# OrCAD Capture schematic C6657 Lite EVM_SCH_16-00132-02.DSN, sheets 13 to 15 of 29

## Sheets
13 PAGE13 : DSP_SERDES_PORTS: size C; title: DSP SERDES PORTS
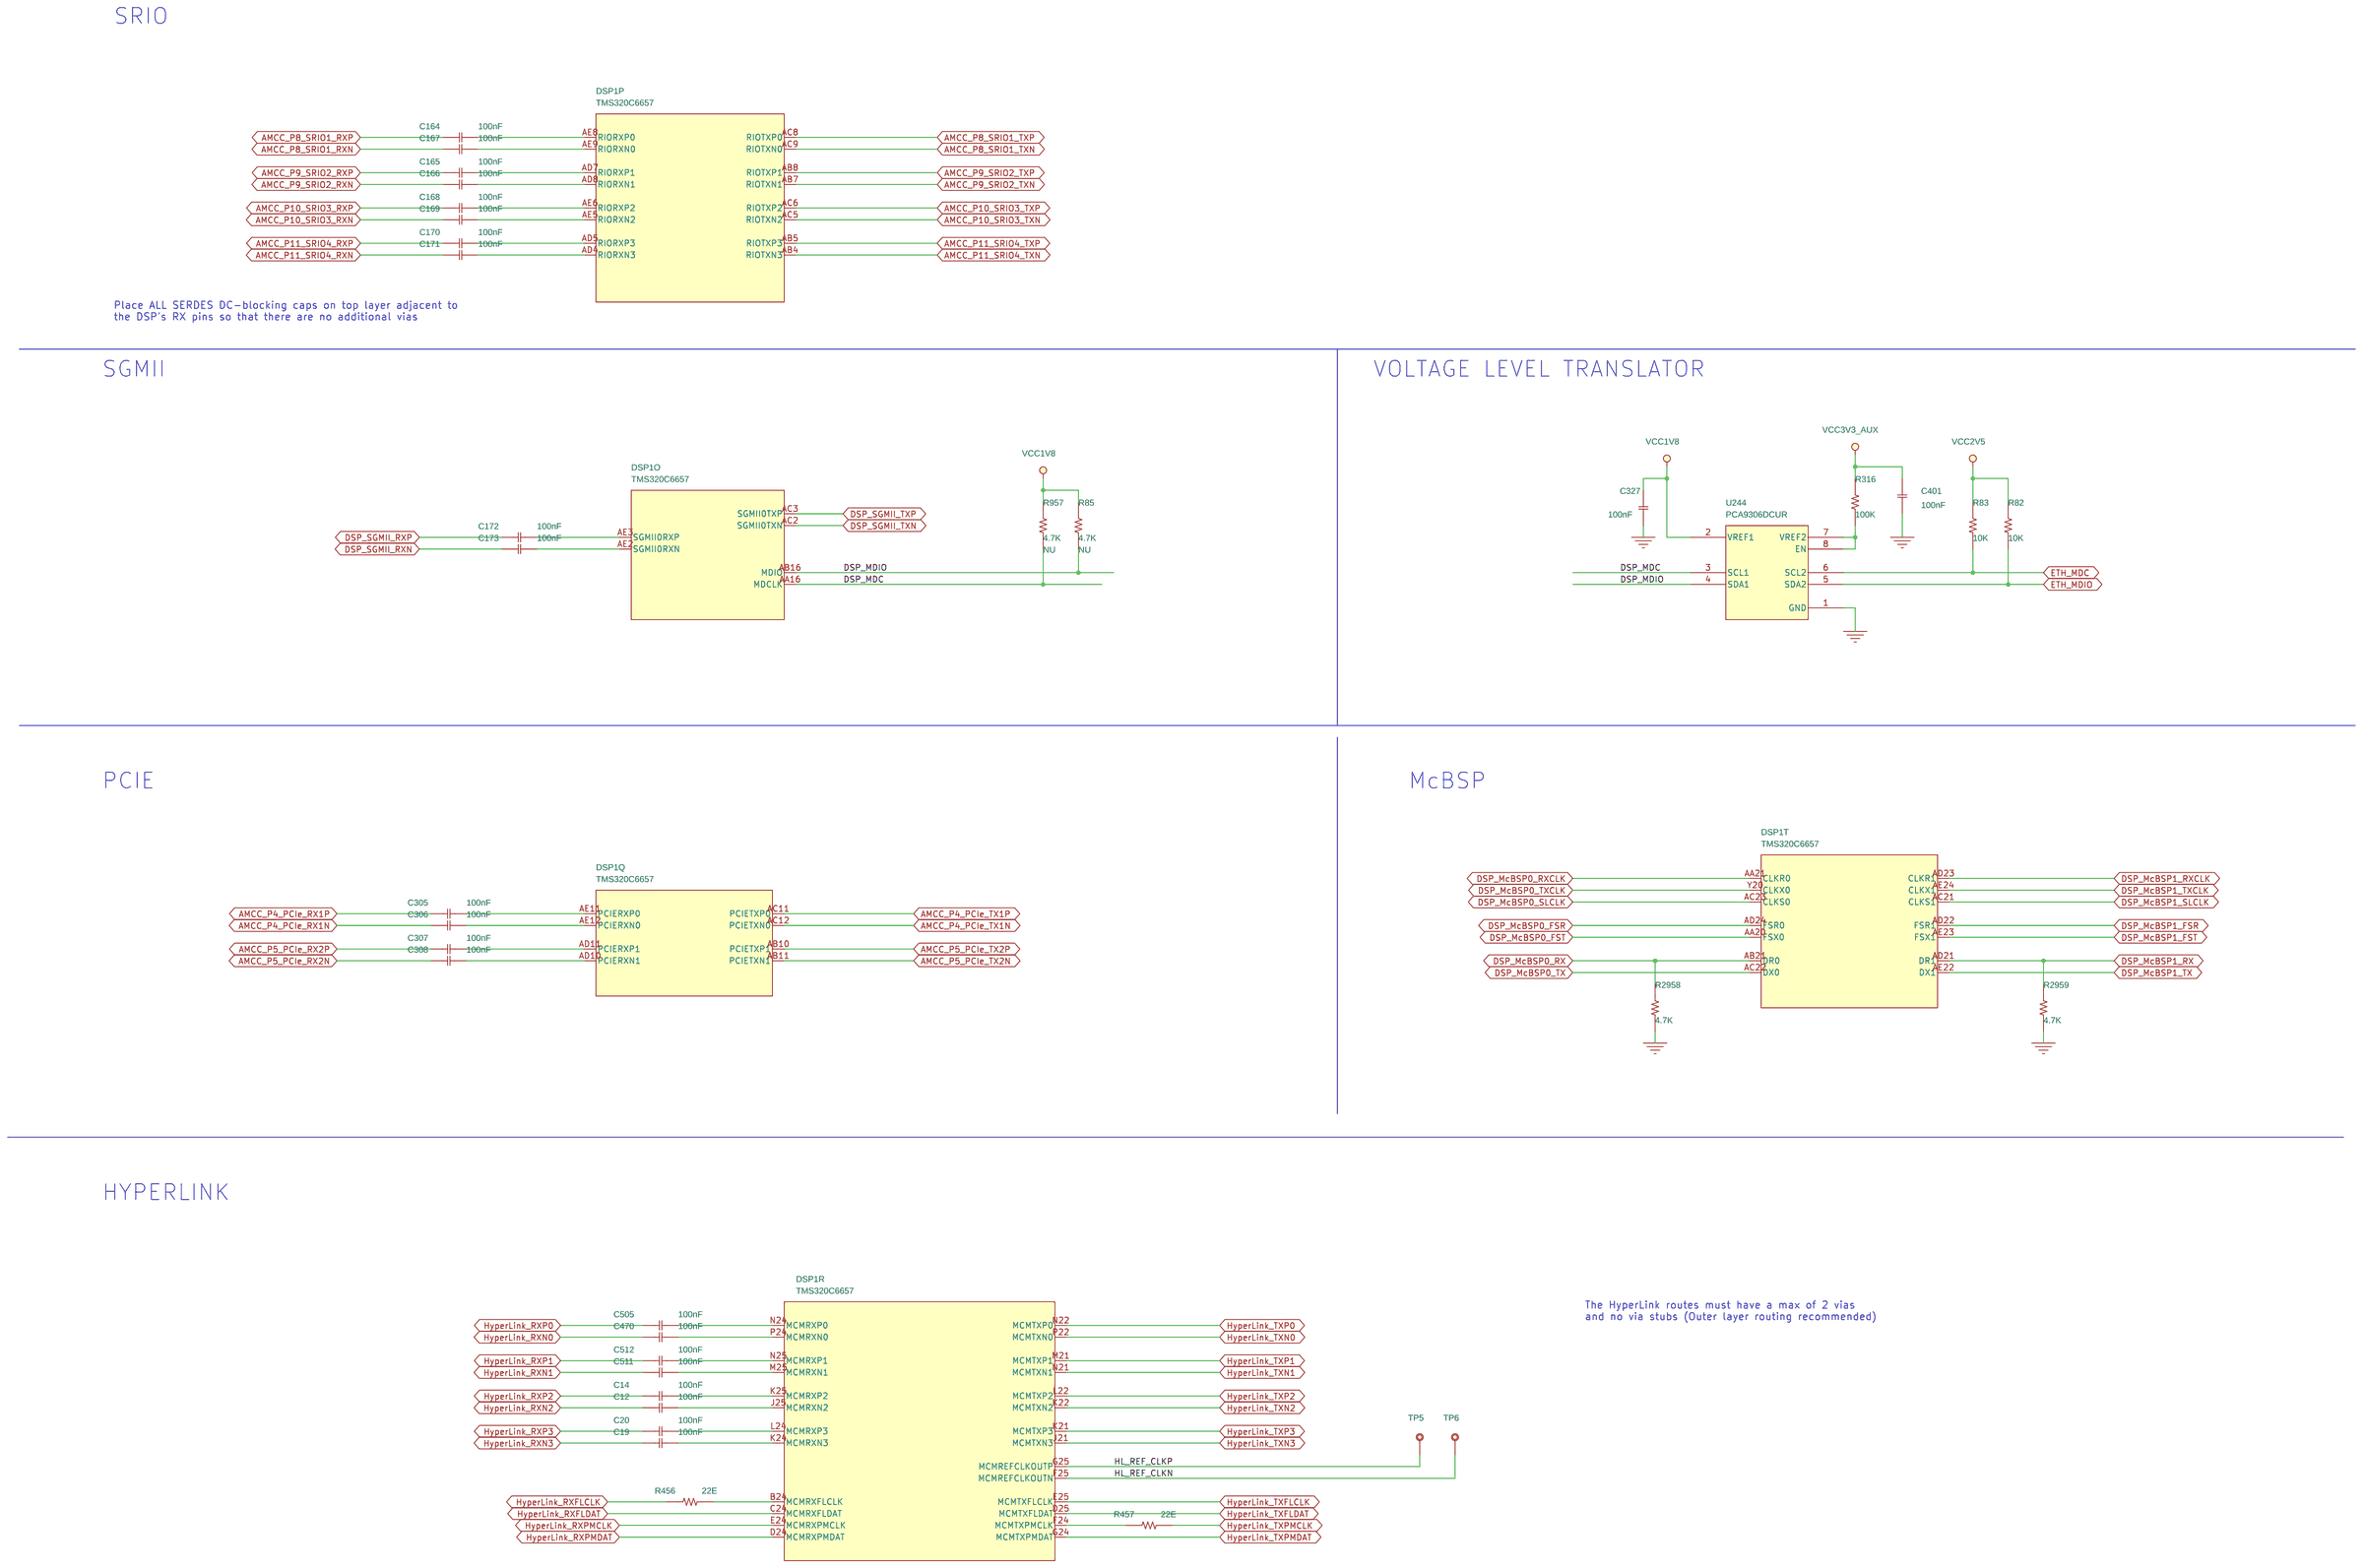
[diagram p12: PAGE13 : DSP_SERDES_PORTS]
14 PAGE27 : POWER SUPPLY 1: size C; title: POWER SUPPLY 1
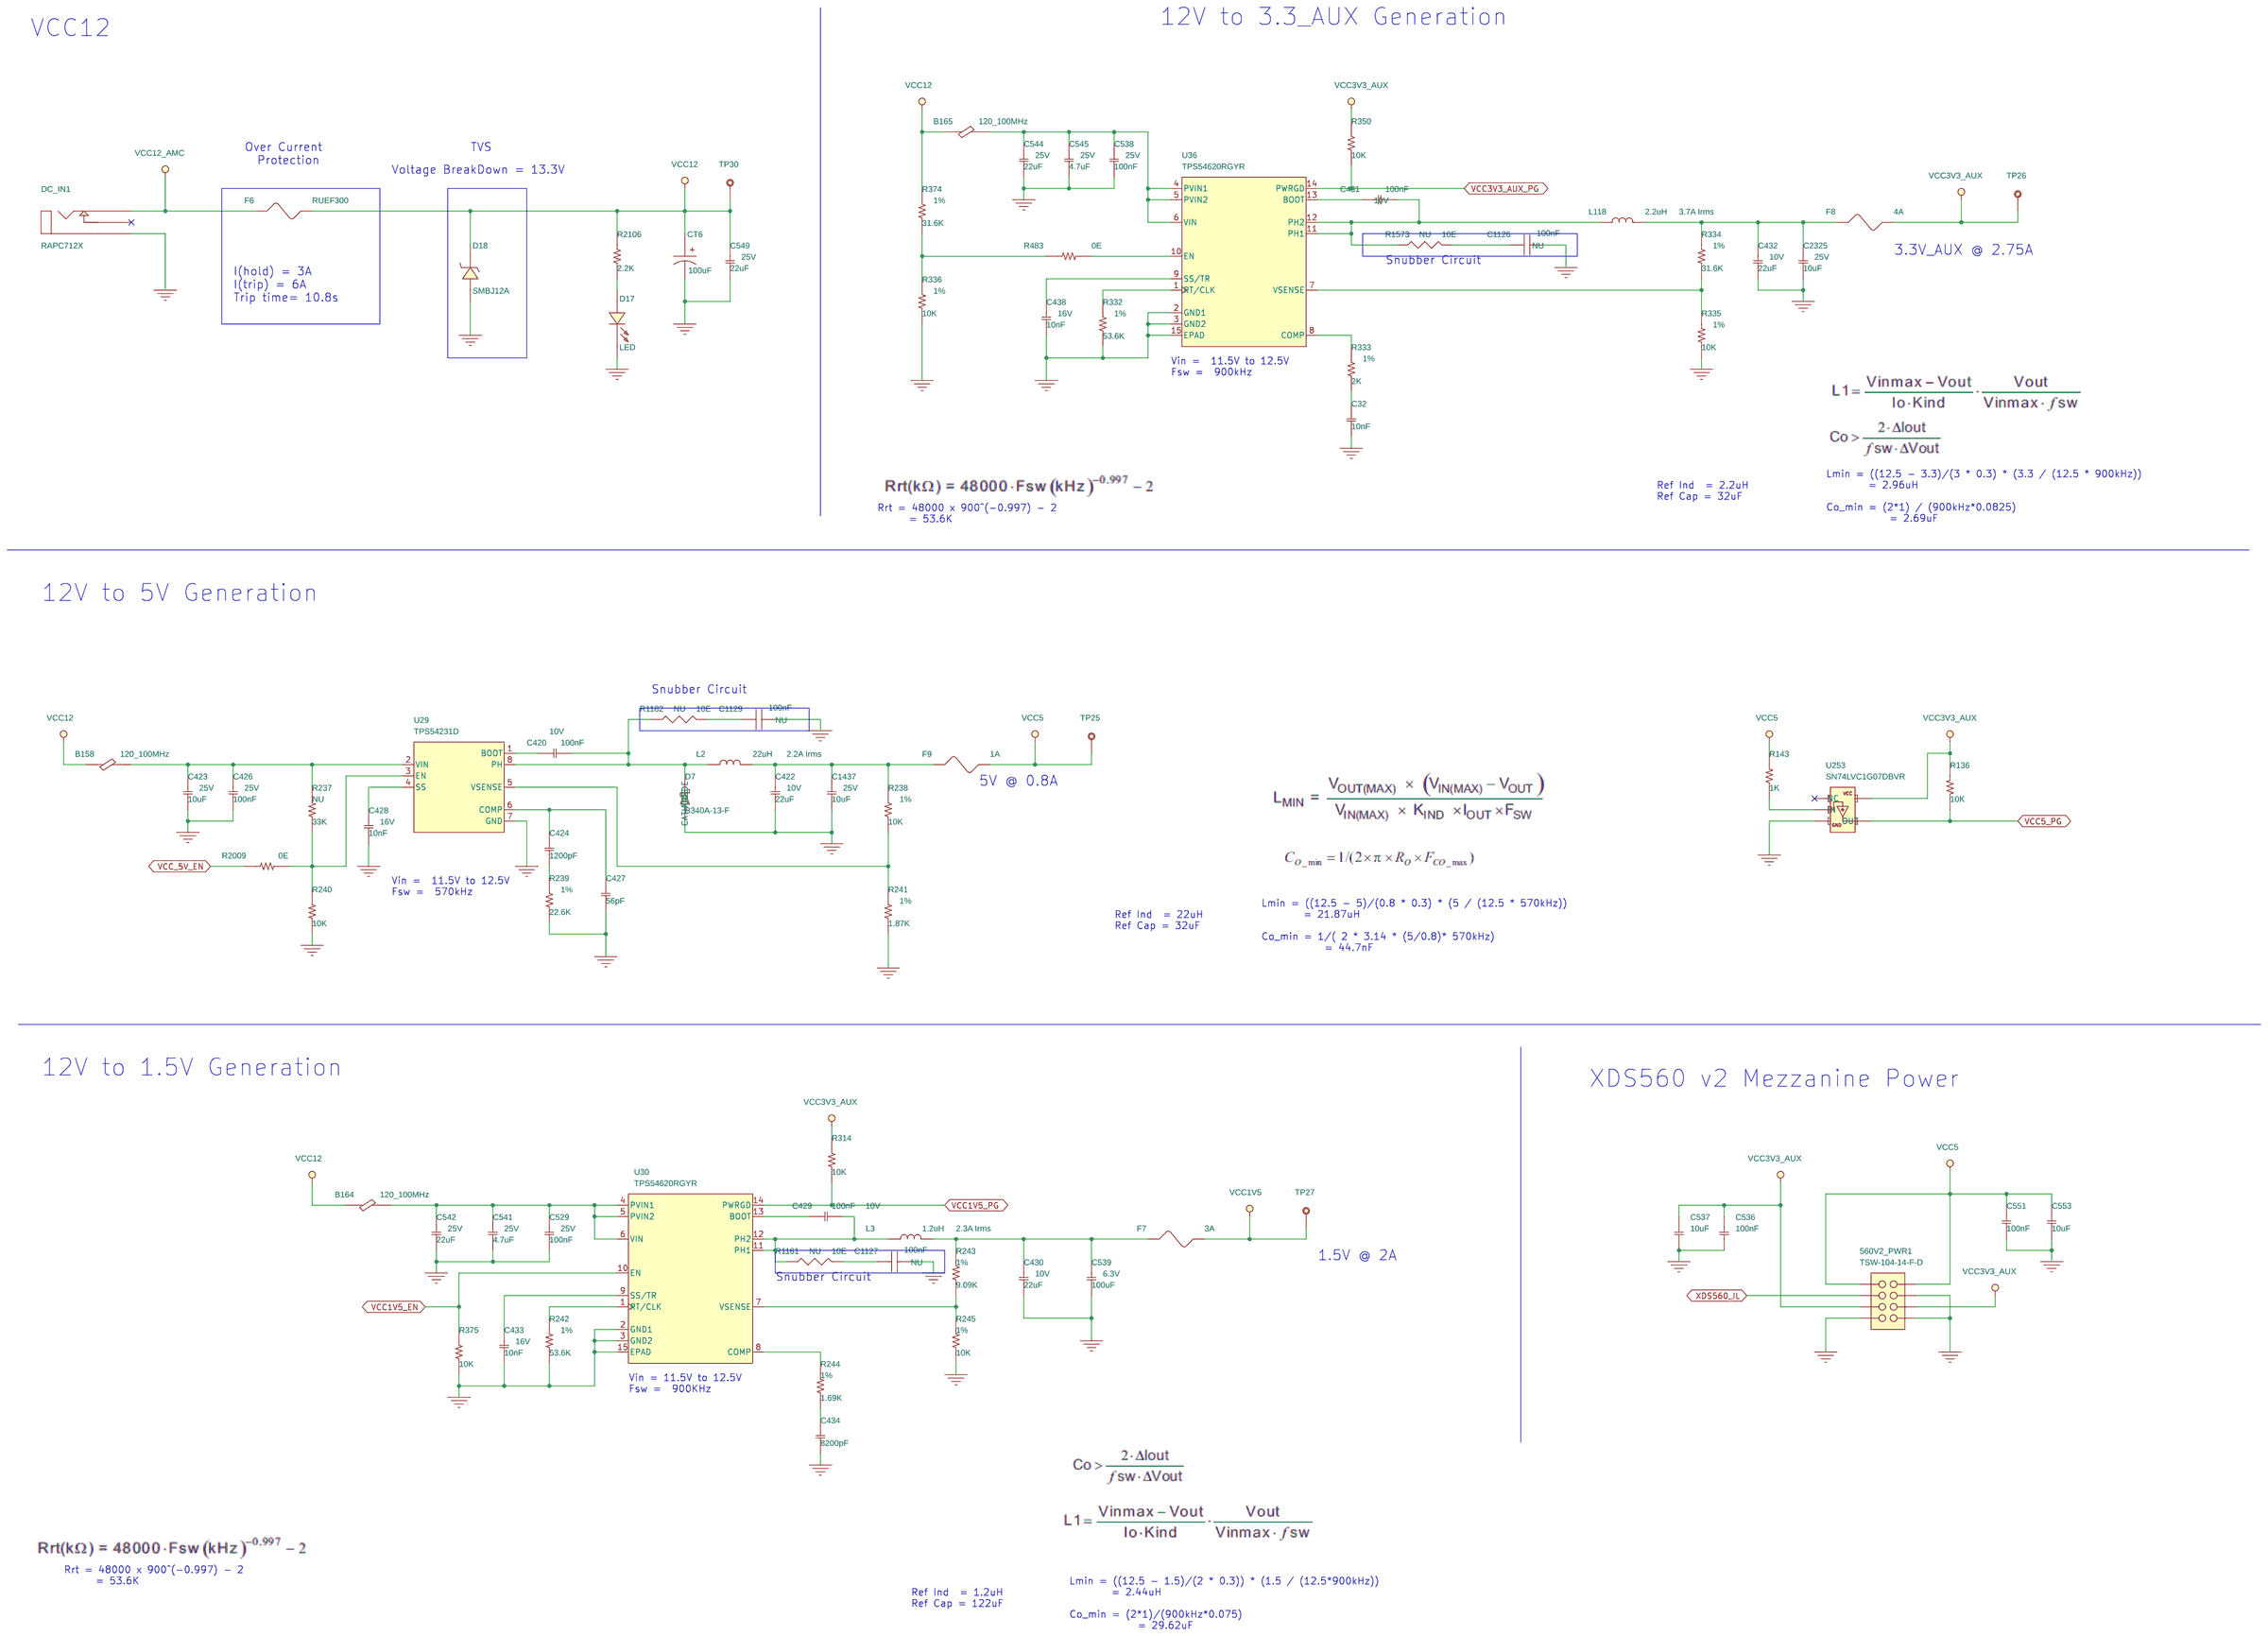
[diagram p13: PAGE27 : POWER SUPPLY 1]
15 PAGE28 : POWER SUPPLY 2: size C; title: POWER SUPPLY 2
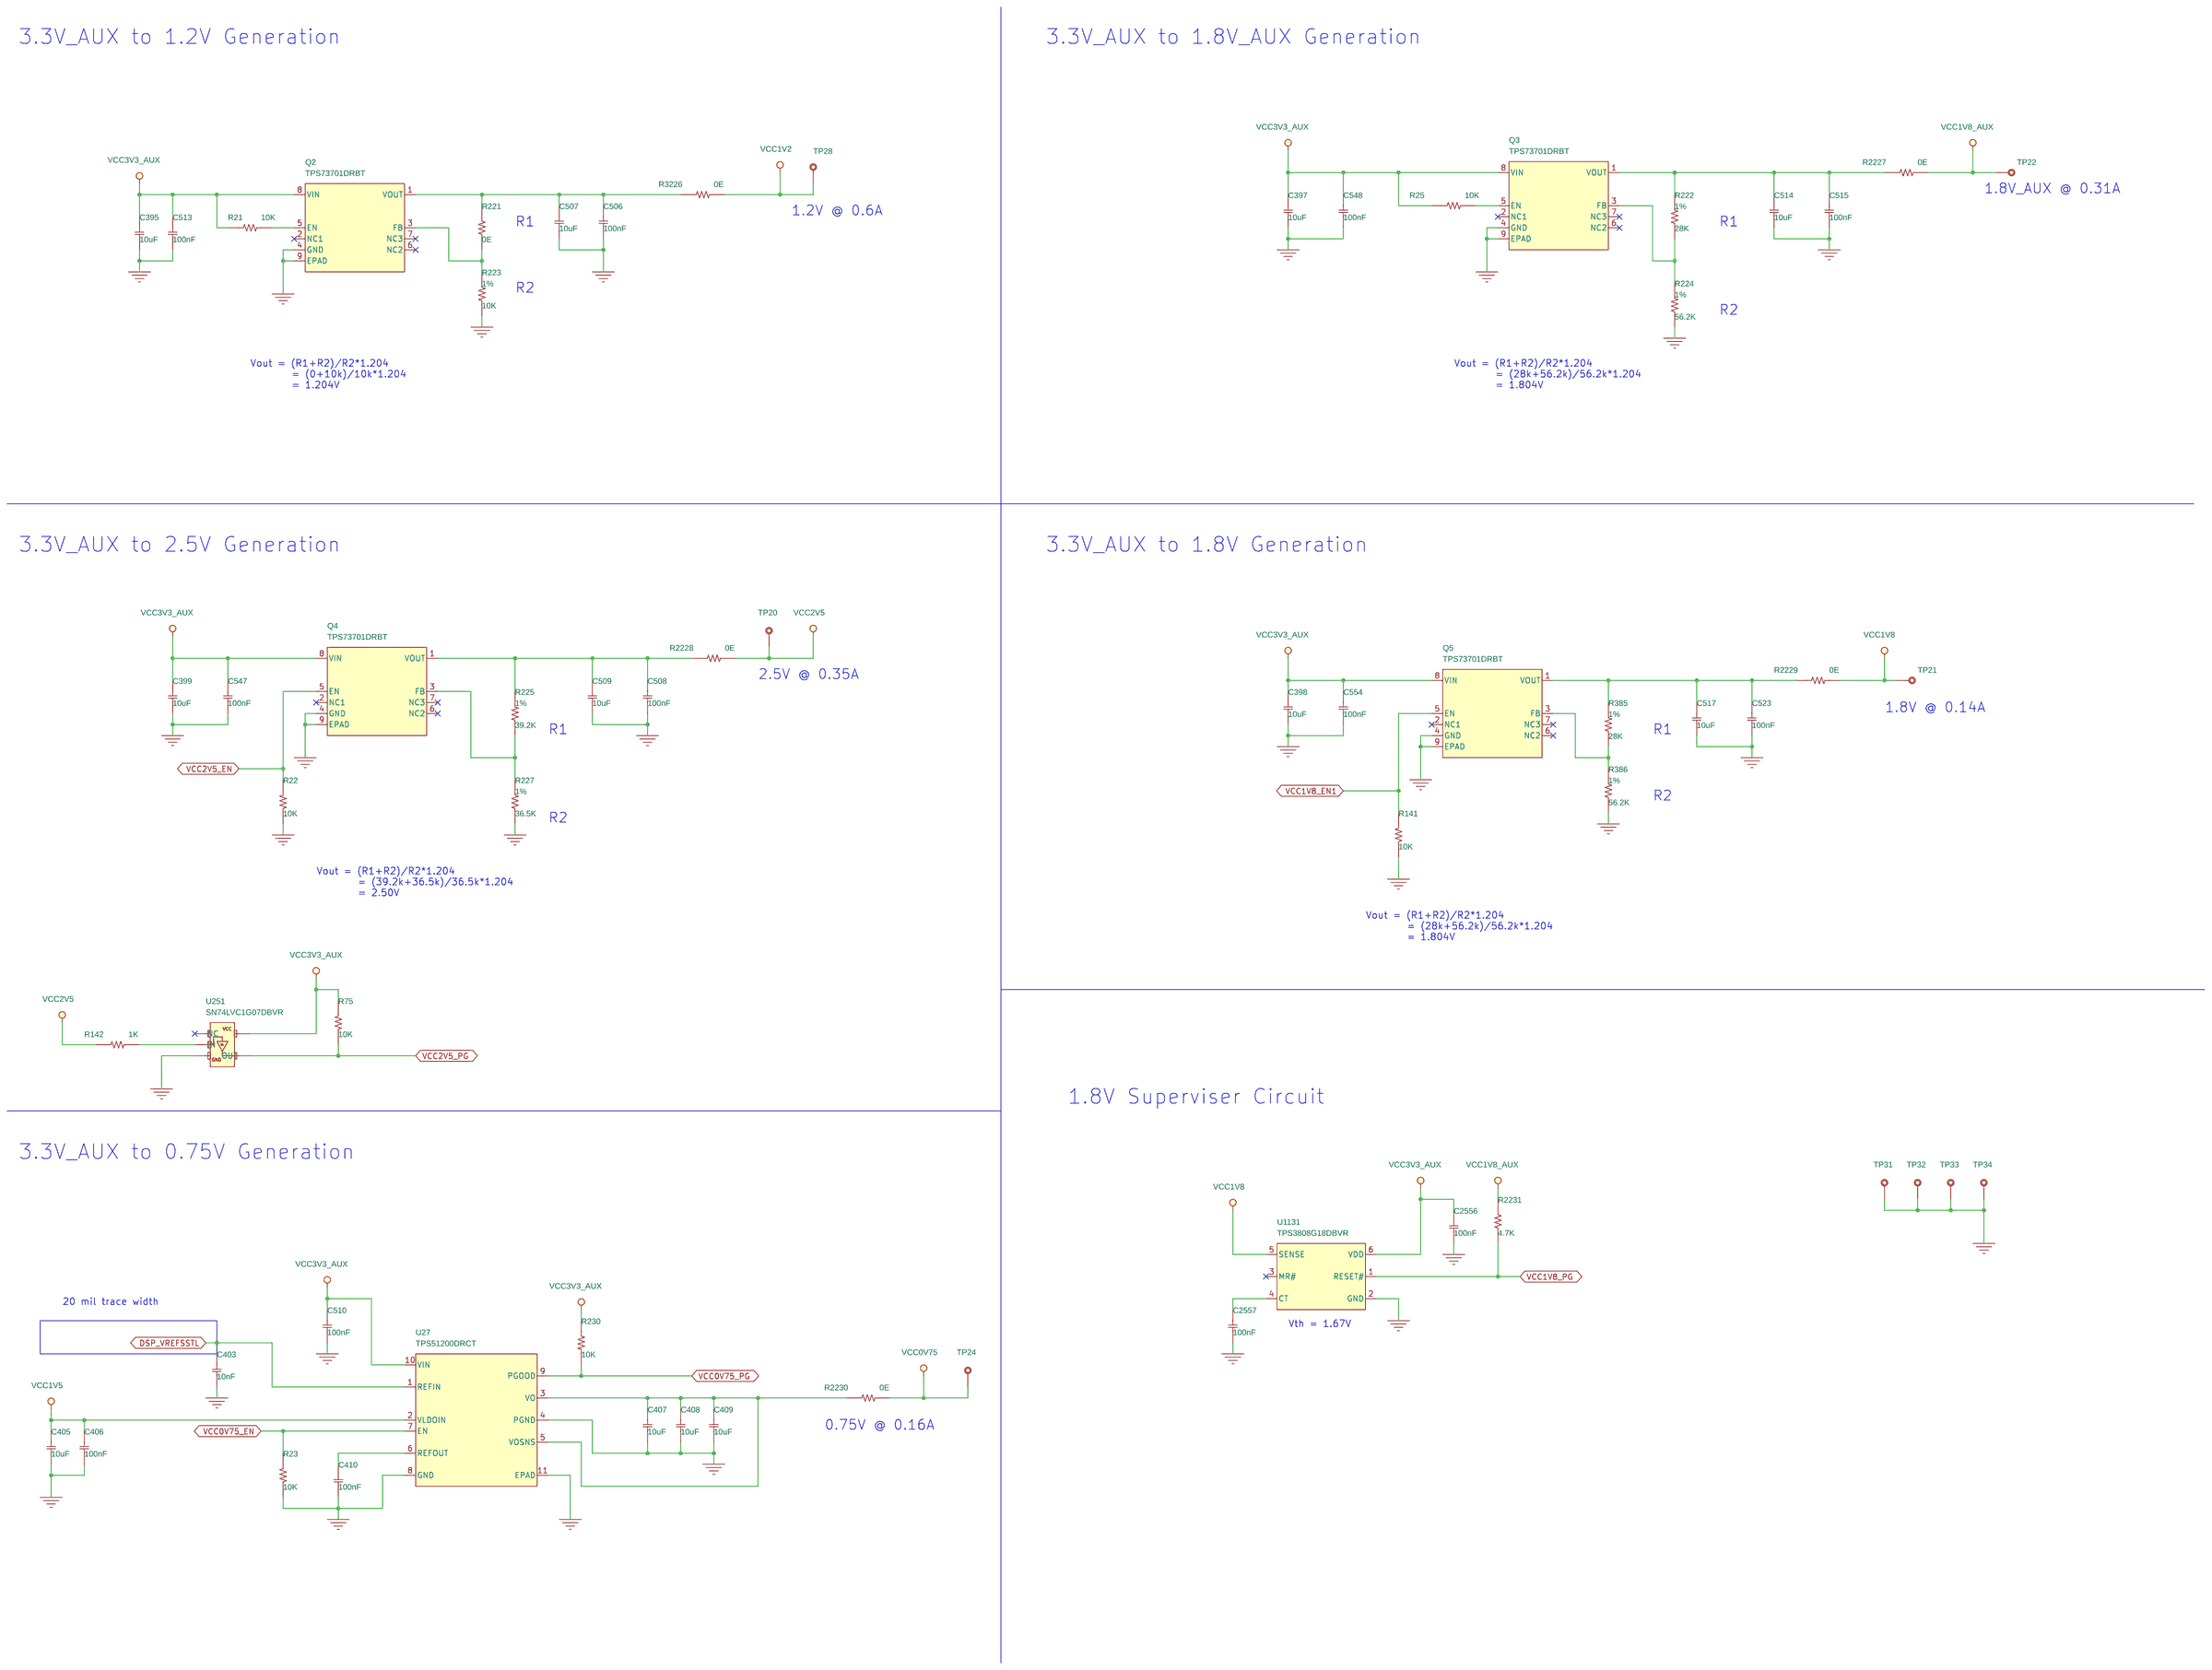
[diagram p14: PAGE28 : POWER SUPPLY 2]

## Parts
sheet PAGE13 : DSP_SERDES_PORTS
C12  100nF  [C0402]
C14  100nF  [C0402]
C19  100nF  [C0402]
C20  100nF  [C0402]
C164  100nF  [C0402]
C165  100nF  [C0402]
C166  100nF  [C0402]
C167  100nF  [C0402]
C168  100nF  [C0402]
C169  100nF  [C0402]
C170  100nF  [C0402]
C171  100nF  [C0402]
C172  100nF  [C0402]
C173  100nF  [C0402]
C305  100nF  [C0402]
C306  100nF  [C0402]
C307  100nF  [C0402]
C308  100nF  [C0402]
C327  100nF  [C0402]
C401  100nF  [C0402]
C470  100nF  [C0402]
C505  100nF  [C0402]
C511  100nF  [C0402]
C512  100nF  [C0402]
R82  10K  [R0402]
R83  10K  [R0402]
R85  4.7K  [R0402]
R316  100K  [R0402]
R456  22E  [R0402]
R457  22E  [R0402]
R957  4.7K  [R0402]
R2958  4.7K  [R0402]
R2959  4.7K  [R0402]
TP5  Test Point  [TP-S40]
TP6  Test Point  [TP-S40]
U244  PCA9306DCUR  [SOIC_8P_20_79X122]
sheet PAGE25 : DSP_POWER 2
DSP1  TMS320C6657  [BGA80P_38X38_625_SKT_EINF]  (sections A,B,C,D,E,F,G,H,I,J,K,L,M,N,O,P,Q,R,S,T)
sheet PAGE27 : POWER SUPPLY 1
560V2_PWR1  TSW-104-14-F-D  [HD_4x2P_100_D]
B158  120_100MHz  [L0603]
B164  120_100MHz  [L0603]
B165  120_100MHz  [L0603]
C32  10nF  [C0402]
C420  100nF  [C0402]
C422  22uF  [C0805]
C423  10uF  [C0805]
C424  1200pF  [C0402]
C426  100nF  [C0402]
C427  56pF  [C0603]
C428  10nF  [C0402]
C429  100nF  [C0402]
C430  22uF  [C0805]
C431  100nF  [C0402]
C432  22uF  [C0805]
C433  10nF  [C0402]
C434  8200pF  [C0603]
C438  10nF  [C0402]
C529  100nF  [C0402]
C536  100nF  [C0402]
C537  10uF  [C0603]
C538  100nF  [C0402]
C539  100uF  [C1206-1]
C541  4.7uF  [C0805]
C542  22uF  [C1206-1]
C544  22uF  [C1206-1]
C545  4.7uF  [C0805]
C549  22uF  [C1206-1]
C551  100nF  [C0402]
C553  10uF  [C0805]
C1126  100nF  [C0402]
C1127  100nF  [C0402]
C1129  100nF  [C0402]
C1437  10uF  [C0805]
C2325  10uF  [C0805]
CT6  100uF  [CT7343]
D7  B340A-13-F  [DIODE_2P_158_197X110]
D17  LED  [LED_LTST-C171]
D18  SMBJ12A  [DIO_DO214AA_SMB]
DC_IN1  RAPC712X  [CON_RAPC712_PWRJACK]
F6  RUEF300  [PTC_RUEF300]
F7  F0603E3R00FSTR  [FUSE_C0603]
F8  MFU0603FF04000P100  [FUSE_C0603]
F9  F0603E1R00FSTR  [FUSE_C0603]
L2  22uH  [IND_NR8040]
L3  1.2uH  [IND_NRG4026]
L118  2.2uH  [IND_NR6028]
R136  10K  [R0402]
R143  1K  [R0402]
R237  33K  [R0402]
R238  10K  [R0402]
R239  22.6K  [R0603]
R240  10K  [R0402]
R241  1.87K  [R0603]
R242  53.6K  [R0402]
R243  9.09K  [R0603]
R244  1.69K  [R0603]
R245  10K  [R0402]
R314  10K  [R0402]
R332  53.6K  [R0402]
R333  2K  [R0402]
R334  31.6K  [R0402]
R335  10K  [R0402]
R336  10K  [R0402]
R350  10K  [R0402]
R374  31.6K  [R0402]
R375  10K  [R0402]
R483  0E  [R0402]
R1181  10E  [R0402]
R1182  10E  [R0402]
R1573  10E  [R0402]
R2009  0E  [R0402]
R2106  2.2K  [R0402]
TP25  Test Point  [TP-S40]
TP26  Test Point  [TP-S40]
TP27  Test Point  [TP-S40]
TP30  Test Point  [TP-S40]
U29  TPS54231D  [SOIC_8P_50_193x236]
U30  TPS54620RGYR  [QFN_14P_20_138x138_TP79]
U36  TPS54620RGYR  [QFN_14P_20_138x138_TP79]
U253  SN74LVC1G07DBVR  [SOT-23_5P]
sheet PAGE28 : POWER SUPPLY 2
C395  10uF  [C0603]
C397  10uF  [C0603]
C398  10uF  [C0603]
C399  10uF  [C0603]
C403  10nF  [C0402]
C405  10uF  [C0603]
C406  100nF  [C0402]
C407  10uF  [C0603]
C408  10uF  [C0603]
C409  10uF  [C0603]
C410  100nF  [C0402]
C506  100nF  [C0402]
C507  10uF  [C0603]
C508  100nF  [C0402]
C509  10uF  [C0603]
C510  100nF  [C0402]
C513  100nF  [C0402]
C514  10uF  [C0603]
C515  100nF  [C0402]
C517  10uF  [C0603]
C523  100nF  [C0402]
C547  100nF  [C0402]
C548  100nF  [C0402]
C554  100nF  [C0402]
C2556  100nF  [C0402]
C2557  100nF  [C0402]
Q2  TPS73701DRBT  [QFN_8P_26_118x118]
Q3  TPS73701DRBT  [QFN_8P_26_118x118]
Q4  TPS73701DRBT  [QFN_8P_26_118x118]
Q5  TPS73701DRBT  [QFN_8P_26_118x118]
R21  10K  [R0402]
R22  10K  [R0402]
R23  10K  [R0402]
R25  10K  [R0402]
R75  10K  [R0402]
R141  10K  [R0402]
R142  1K  [R0402]
R221  0E  [R0402]
R222  28K  [R0603]
R223  10K  [R0402]
R224  56.2K  [R0603]
R225  39.2K  [R0603]
R227  36.5K  [R0603]
R230  10K  [R0402]
R385  28K  [R0603]
R386  56.2K  [R0603]
R2227  0E  [R0402]
R2228  0E  [R0402]
R2229  0E  [R0402]
R2230  0E  [R0402]
R2231  4.7K  [R0402]
R3226  0E  [R0402]
TP20  Test Point  [TP-S40]
TP21  Test Point  [TP-S40]
TP22  Test Point  [TP-S40]
TP24  Test Point  [TP-S40]
TP28  Test Point  [TP-S40]
TP31  Test Point  [TP-S40]
TP32  Test Point  [TP-S40]
TP33  Test Point  [TP-S40]
TP34  Test Point  [TP-S40]
U27  TPS51200DRCT  [QFN10P_20_118x118_TP94x65V5]
U251  SN74LVC1G07DBVR  [SOT-23_5P]
U1131  TPS3808G18DBVR  [SOT23_6]

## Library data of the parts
C12 C14 C19 C20 C164-C173 C305-C308 C327 C401 C406 C410 C470 C505 C506 C508 C510-C513 C515 C523 C536 C547 C548 C551 C554 C2556 C2557 = 11_C_0: CAP CER 0.1UF 10V 10% X5R 0402; Alt Mfg: Murata; Alt Mfg Part#: GRM155R61A104KA01D; Manufacture Part Number: 2238 787 15649||CC0402KRX7R7BB104; Mfg: Yageo; Mfg Part#: CC0402KRX5R6BB104; Oper. Temp. Range: -55C to 85C; Package: 0402; ProcessType: SMT; RoHS: Yes; Tolerance: 10%; Vendor: DigiKey; Vendor Part#: 311-1336-1-ND; eI Part#: 03_00021_02
R21-R23 R25 R75 R82 R83 R136 R141 R223 R230 R238 R240 R245 R314 R335 R336 R350 R375 = 10_R_0: RES 10.0K OHM 1/10W 1% 0402 SMD; Alt Mfg: Yageo; Alt Mfg Part#: RC0402FR-0710KL; Manufacture Part Number: 0402WGF1002TCE||RM04FTN1002; Mfg: Panasonic - ECG; Mfg Part#: ERJ-2RKF1002X; Oper. Temp. Range: -55C ~ 125C; Package: 0402; ProcessType: SMT; Remark: Alt part is 1/16W; RoHS: Yes; Tolerance: 1%; Vendor: DigiKey; Vendor Part#: P10.0KLCT-ND; eI Part#: 02_00027_01
R85 R957 = 10_R_0: RES 4.7K OHM 1/10W 5% 0402 SMD; Alt Mfg: Yageo; Alt Mfg Part#: RC0402JR-074K7L; Manufacture Part Number: 0402WGJ0472TCE||RC0402JR-074K7L||RM04JTN472; Mfg: Panasonic - ECG; Mfg Part#: ERJ-2GEJ472X; Mounting Status: NU; Mounting _Status: NU; Oper. Temp. Range: -55C to 125C; Package: 0402; ProcessType: SMT; Remark: Alt part is 1/16W; RoHS: Yes; Tolerance: 5%; Vendor: DigiKey; Vendor Part#: P4.7KJCT-ND; eI Part#: 02_00023_01
R316 = 10_R_0: RES 100K OHM 1/10W 1% 0402 SMD; Alt Mfg: Yageo; Alt Mfg Part#: RC0402FR-07100KL; Manufacture Part Number: 0402WGF1003TCE||RM04FTN1003; Mfg: Panasonic - ECG; Mfg Part#: ERJ-2RKF1003X; Oper. Temp. Range: ±100ppm/°C; Package: 0402; ProcessType: SMT; RoHS: Yes; Tolerance: 1%; Vendor: DigiKey; Vendor Part#: P100KLCT-ND; eI Part#: 02_00262_01
R456 R457 = 10_R_0: RES 22 OHM 1/10W 5% 0402 SMD; Mfg: Panasonic - ECG; Mfg Part#: ERJ-2GEJ220X; Oper. Temp. Range: -55C to 125C; Package: 0402; ProcessType: SMT; Remark: Alt part is 1/16W; RoHS: Yes; Tolerance: 5%; Vendor: DigiKey; Vendor Part#: P22JCT-ND; eI Part#: 02_00233_01
R2231 R2958 R2959 = 10_R_0: RES 4.7K OHM 1/10W 5% 0402 SMD; Alt Mfg: Yageo; Alt Mfg Part#: RC0402JR-074K7L; Manufacture Part Number: 0402WGJ0472TCE||RC0402JR-074K7L||RM04JTN472; Mfg: Panasonic - ECG; Mfg Part#: ERJ-2GEJ472X; Oper. Temp. Range: -55C to 125C; Package: 0402; ProcessType: SMT; Remark: Alt part is 1/16W; RoHS: Yes; Tolerance: 5%; Vendor: DigiKey; Vendor Part#: P4.7KJCT-ND; eI Part#: 02_00023_01
TP5 TP6 TP20-TP22 TP24-TP28 TP30-TP34 = 00_TP-S40_0: TEST PAD TP-S40; Mfg: --NA--; Mfg Part#: --NA--; Oper. Temp. Range: --NA--; Package: --NA--; ProcessType: SMT; RoHS: Yes; Vendor: --NA--; Vendor Part#: --NA--; eI Part#: --NA--
U244 = PCA9306: IC, Dual I2C Voltage Translator; Alt Mfg: NXP Semiconductors; Alt Mfg Part#: PCA9306DC1,125; Mfg: Texas Instruments; Oper. Temp. Range: -40C to 85C; Package: 8-VSSOP; RoHS: Yes; Specifications: IC, Dual I2C Voltage Translator; Vendor: Digikey; Vendor Part#: 296-17988-1-ND; eI Part#: 01_00044_01
DSP1 = TMS320C6657: TI DSP, Dual C66x™ DSP Cores; Mfg: Texas Instruments; RoHS: Yes; Vendor: Texas Instruments; eI Part#: 01_00878_01
560V2_PWR1 = CONNECTOR_-_4_X_2: HEADER, 2.54MM, THT VERT, 8WAY; Mfg: Samtec; Oper. Temp. Range: -55C to 125C; RoHS: Yes; Specifications: HEADER, 2.54MM, THT VERT, 8WAY; Vendor: Samtec; eI Part#: 09_00667_01
B158 B164 B165 = 1212_BEAD_0: FERRITE CHIP 120 OHM 2000MA 0603; Manufacture Part Number: BLM18PG121SN1; Mfg: Murata; Mfg Part#: BLM18PG121SN1D; Oper. Temp. Range: -55C to 85C; Package: 0603; ProcessType: SMT; RoHS: Yes; Tolerance: 25%; Vendor: DigiKey; Vendor Part#: 490-1037-1-ND; eI Part#: 04_00023_01
C32 = 11_C_0: CAP 10nF 16V CERAMIC 0402 SMD; Alt Mfg: Murata; Alt Mfg Part#: GRM155R71C103KA01D; Mfg: Panasonic - ECG; Mfg Part#: ECJ-0EB1C103K; Oper. Temp. Range: -55C to 125C; Package: 0402; ProcessType: SMT; RoHS: Yes; Tolerance: 10%; Vendor: DigiKey; Vendor Part#: PCC103BQCT-ND; eI Part#: 03_00025_01
C420 C429 C431 = 11_C_0: CAP CER 0.1UF 10V 10% X5R 0402; Alt Mfg: Murata; Alt Mfg Part#: GRM155R61A104KA01D; Manufacture Part Number: 2238 787 15649||CC0402KRX7R7BB104; Mfg: Yageo; Mfg Part#: CC0402KRX5R6BB104; Oper. Temp. Range: -55C to 85C; Package: 0402; ProcessType: SMT; RoHS: Yes; Tolerance: 10%; Vendor: DigiKey; Vendor Part#: 311-1336-1-ND; Voltage: 10V; eI Part#: 03_00021_02
C422 C430 C432 = 11_C_0: CAP CER 22UF 10V X5R 0805; Manufacture Part Number: C0805B226M007T; Mfg: Taiyo Yuden; Mfg Part#: LMK212BJ226MG-T; Oper. Temp. Range: -55C to 85C; Package: 0805; ProcessType: SMT; RoHS: Yes; Tolerance: 20%; Vendor: DigiKey; Vendor Part#: 587-1958-1-ND; Voltage: 10V; eI Part#: 03_00263_01
C423 C553 C1437 C2325 = 11_C_0: CAP CER 10UF 25V 10% X5R 0805; Alt Mfg: TDK Corporation; Alt Mfg Part#: C2012X5R1E106K; Manufacture Part Number: GRM21BR61C106K; Mfg: Murata; Mfg Part#: GRM21BR61E106KA73L; Oper. Temp. Range: -55C to 85C; Package: 0805; ProcessType: SMT; RoHS: Yes; Vendor: DigiKey; Vendor Part#: 490-5523-1-ND; Voltage: 25V; eI Part#: 03_00165_04
C424 = 11_C_0: CAP CER 1200PF 50V 10% X7R 0402; Manufacture Part Number: 2238 586 15624; Mfg: Murata; Mfg Part#: GRM155R71H122KA01D; Oper. Temp. Range: -55C ~ 125C; Package: 0402; ProcessType: SMT; RoHS: Yes; Tolerance: 10%; Vendor: DigiKey; Vendor Part#: 490-1304-1-ND; Voltage: 50V; eI Part#: 03_00151_01
C426 C529 C538 = 11_C_0: CAP CER 0.1UF 25V 10% X5R 0402; Manufacture Part Number: 2238 787 15649||CC0402KRX7R7BB104; Mfg: Taiyo Yuden; Mfg Part#: TMK105BJ104KV-F; Oper. Temp. Range: -55C to 85C; Package: 0402; ProcessType: SMT; RoHS: Yes; Tolerance: 10%; Vendor: DigiKey; Vendor Part#: 587-1456-1-ND; Voltage: 25V; eI Part#: 03_00470_01
C427 = 11_C_0: CAP CER 56PF 50V 5% NP0 0603; Manufacture Part Number: 223886715569; Mfg: Yageo; Mfg Part#: CC0603JRNP09BN560; Oper. Temp. Range: -55C ~ 125C; Package: 0603; ProcessType: SMT; RoHS: Yes; Tolerance: 5%; Vendor: DigiKey; Vendor Part#: 311-1066-1-ND; Voltage: 50V; eI Part#: 03_00144_03
C428 C433 = 11_C_0: CAP 10nF 16V CERAMIC 0402 SMD; Alt Mfg: Murata; Alt Mfg Part#: GRM155R71C103KA01D; Manufacture Part Number: C1005X7R1C103K||2238 787 15636||CC0402KRX7R7BB103; Mfg: Panasonic - ECG; Mfg Part#: ECJ-0EB1C103K; Oper. Temp. Range: -55C to 125C; Package: 0402; ProcessType: SMT; RoHS: Yes; Tolerance: 10%; Vendor: DigiKey; Vendor Part#: PCC103BQCT-ND; Voltage: 16V; eI Part#: 03_00025_01
C434 = 11_C_0: CAP CER 8200PF 50V 10% X7R 0603; Manufacture Part Number: 223858615635; Mfg: AVX Corporation; Mfg Part#: 06035C822KAT2A; Oper. Temp. Range: -55C ~ 125C; Package: 0603; ProcessType: SMT; RoHS: Yes; Tolerance: 10%; Vendor: DigiKey; Vendor Part#: 478-1226-1-ND; eI Part#: 03_00232_03
C438 = 11_C_0: CAP 10nF 16V CERAMIC 0402 SMD; Alt Mfg: Murata; Alt Mfg Part#: GRM155R71C103KA01D; Mfg: Panasonic - ECG; Mfg Part#: ECJ-0EB1C103K; Oper. Temp. Range: -55C to 125C; Package: 0402; ProcessType: SMT; RoHS: Yes; Tolerance: 10%; Vendor: DigiKey; Vendor Part#: PCC103BQCT-ND; Voltage: 16V; eI Part#: 03_00025_01
C395 C397-C399 C405 C407-C409 C507 C509 C514 C517 C537 = 11_C_0: CAP CER 10UF 6.3V 20% X5R 0603; Manufacture Part Number: C1608X5R0J106MT||2255 206 13776||CC0603MRX5R5BB106; Mfg: Murata; Mfg Part#: GRM188R60J106ME47D; Oper. Temp. Range: -55C to 85C; Package: 0603; ProcessType: SMT; RoHS: Yes; Tolerance: 20%; Vendor: DigiKey; Vendor Part#: 490-3896-1-ND; eI Part#: 03_00058_03
C539 = 11_C_0: CAP CER 100UF 6.3V 20% X5R 1206; Manufacture Part Number: JMK316BJ107ML-T; Mfg: Taiyo Yuden; Mfg Part#: JMK316BJ107ML-T; Oper. Temp. Range: -55C to 85C; Package: 1206; ProcessType: SMT; RoHS: Yes; Tolerance: 20%; Vendor: DigiKey; Vendor Part#: 587-1963-1-ND; Voltage: 6.3V; eI Part#: 03_00380_04
C541 C545 = 11_C_0: CAP CER 4.7UF 25V X5R 0805; Manufacture Part Number: GRM188R60J475K||C1608X5R0J475KT; Mfg: Taiyo Yuden; Mfg Part#: TMK212BJ475KG-T; Oper. Temp. Range: -55C to 85C; Package: 0805; ProcessType: SMT; RoHS: Yes; Tolerance: 10%; Vendor: DigiKey; Vendor Part#: 587-1782-1-ND; Voltage: 25V; eI Part#: 03_00066_02
C542 C544 C549 = 11_C_0: CAP CER 22UF 25V 10% X5R 1206; Manufacture Part Number: KC30R1C226M-T; Mfg: Murata; Mfg Part#: GRM31CR61E226KE15L; Oper. Temp. Range: -55C to 85C; Package: 1206; ProcessType: SMT; RoHS: Yes; Tolerance: 10%; Vendor: DigiKey; Vendor Part#: 490-5527-1-ND; Voltage: 25V; eI Part#: 03_00442_01
C1126 C1127 C1129 = CAP_NP: CAP CER 0.1UF 10V 10% X5R 0402; Alt Mfg: Murata; Alt Mfg Part#: GRM155R61A104KA01D; Mfg: Yageo; Mfg Part#: CC0402KRX5R6BB104; Mounting Status: NU; Mounting_Status: NU; Oper. Temp. Range: -55C to 85C; Package: 0402; RoHS: Yes; Specifications: CAP CER 0.1UF 10V X5R 0402; Vendor: DigiKey; Vendor Part#: 311-1336-1-ND; eI Part#: 03_00021_02
CT6 = CAP_POL: CAP TANT 100UF 25V 10% SMD; Mfg: Kemet; Mfg Part#: T491X107K025ZT; Oper. Temp. Range: -55C to 125C; Package: 7343; RoHS: Yes; Specifications: CAP TANT 100UF 25V 10% SMD; Vendor: DigiKey; Vendor Part#: 399-5175-1-ND; Voltage: 25V; eI Part#: 03_00301_01
D7 = 130_Schottky_SMA-1_0: DIODE SCHOTTKY 3A 40V SMA; Manufacture Part Number: B340A-E3; Mfg: Diodes Inc; Oper. Temp. Range: -55C to 85C; Package: DO-214AC; ProcessType: SMT; RoHS: Yes; Specifications: DIODE SCHOTTKY 3A 40V SMA; Vendor: DigiKey; Vendor Part#: B340A-FDICT-ND; eI Part#: 06_00002_01
D17 = LED: LED GREEN CLEAR THIN 0805 SMD; Mfg: Lite-On Inc; Mfg Part#: LTST-C171KGKT; Oper. Temp. Range: -25 to +85C; Package: 0805; RoHS: Yes; Specifications: LED GREEN CLEAR THIN 0805 SMD; Vendor: DigiKey; Vendor Part#: 160-1426-1-ND; eI Part#: 06_00086_01
D18 = Zener_Diode: TVS 600W 12V UNIDIRECT SMB; Alt Mfg: Diodes Inc; Alt Mfg Part#: SMBJ12A-13-F; Mfg: Micro Commercial Co; Mfg Part#: SMBJ12A-TP; Package: DO-214AA, SMB; RoHS: Yes; Specifications: TVS 600W 12V UNIDIRECT SMB; Vendor: DigiKey; Vendor Part#: SMBJ12A-TPMSCT-ND; eI Part#: 06_00088_01
DC_IN1 = CONN_JACK_PWR: CONN POWERJACK MINI R/A PCMT; Mfg: Switchcraft; RoHS: Yes; Specifications: CONN POWERJACK MINI R/A PCMT; Vendor: DigiKey; Vendor Part#: SC237-ND; eI Part#: 09_00017_01
F6 = Fuse: POLYSWITCH RUE SERIES 3.00A; Mfg: Tyco Electronics; Package: Radial; Specifications: POLYSWITCH RUE SERIES 3.00A; Vendor Part#: RUEF300-ND; eI Part#: 13_00002_01
F7 = Fuse: FUSE 3.00A 32V FAST THIN 0603; Mfg: AVX Corporation; Oper. Temp. Range: -55°C ~ 125°C; Package: 0603; Rating: 3A; Specifications: FUSE 3.00A 32V FAST THIN 0603; Vendor Part#: 478-2868-1-ND; eI Part#: 13_00020_01
F8 = Fuse: FUSE 4.00A 0603 VFAST SMD; Mfg: Vishay/Beyschlag; Package: 0603; Rating: 4A; Specifications: FUSE 4.00A 0603 VFAST SMD; Vendor Part#: MFU06034.00CT-ND; eI Part#: 13_00021_01
F9 = Fuse: FUSE 1.00A 32V FAST THIN 0603; Mfg: AVX Corporation; Package: 0603; Rating: 1A; Specifications: FUSE 1.00A 32V FAST THIN 0603; Vendor Part#: 478-2862-1-ND; eI Part#: 13_00015_01
L2 = 1211_L_0: INDUCTOR 22UH 2.2A 20% SMD; Current: 2.2A Irms; Manufacture Part Number: IHLM2525CZER220M11; Mfg: Taiyo Yuden; Mfg Part#: NR8040T220M; Oper. Temp. Range: -40°C ~ 105°C; Package: 8.00mm x 8.00mm x 4.00mm; ProcessType: SMT; RoHS: Yes; Tolerance: 20%; Vendor: DigiKey; Vendor Part#: 587-2002-1-ND; eI Part#: 04_00104_01
L3 = 1211_CHOKE_0: INDUCTOR 1.2UH 2.3A 30% SMD; Current: 2.3A Irms; Manufacture Part Number: PCMC063T-3R3MN; Mfg: Taiyo Yuden; Mfg Part#: NRG4026T1R2N; Package: 4.00mm x 4.00mm x 2.60mm; ProcessType: SMT; RoHS: Yes; Tolerance: 30%; Vendor: DigiKey; Vendor Part#: 587-2377-1-ND; eI Part#: 04_00267_01
L118 = 1211_CHOKE_0: INDUCTOR 2.2UH 4.2A 30% SMD; Current: 3.7A Irms; Mfg: Taiyo Yuden; Mfg Part#: NR6028T2R2N; Oper. Temp. Range: -40C to 80C; Package: 6.00mm x 6.00mm x 2.80mm; ProcessType: SMT; RoHS: Yes; Tolerance: 30%; Vendor: DigiKey; Vendor Part#: 587-2098-1-ND; eI Part#: 04_00110_01
R142 R143 = 10_R_0: RES 1.00K OHM 1/10W 1% 0402 SMD; Alt Mfg: Yageo; Alt Mfg Part#: RC0402FR-071KL; MOUNTED: <MOUNTED>; Manufacture Part Number: 0402WGF1001TCE||RM04FTN1001; Mfg: Panasonic - ECG; Mfg Part#: ERJ-2RKF1001X; Oper. Temp. Range: -55C to 125C; Package: 0402; ProcessType: SMT; RoHS: Yes; Tolerance: 1%; Vendor: DigiKey; Vendor Part#: P1.00KLCT-ND; eI Part#: 02_00045_01
R237 = 10_R_0: RES 33K OHM 1/10W 5% 0402 SMD; Alt Mfg: Yageo; Alt Mfg Part#: RC0402JR-0733KL; Manufacture Part Number: 0402WGJ0333TCE||RM04JTN333; Mfg: Panasonic - ECG; Mfg Part#: ERJ-2GEJ333X; Mounting Status: NU; Mounting_Status: NU; Oper. Temp. Range: -55C to 125C; Package: 0402; ProcessType: SMT; Remark: Alt part is 1/16W; RoHS: Yes; Tolerance: 5%; Vendor: DigiKey; Vendor Part#: P33KJCT-ND; eI Part#: 02_00356_01
R239 = 10_R_0: RES 22.6K OHM 1/10W 1% 0603 SMD; Manufacture Part Number: 0603WAF2262T5E||232270462263L; Mfg: Panasonic - ECG; Mfg Part#: ERJ-3EKF2262V; Oper. Temp. Range: -55C ~ 125C; Package: 0603; ProcessType: SMT; RoHS: Yes; Tolerance: 1%; Vendor: DigiKey; Vendor Part#: P22.6KHCT-ND; eI Part#: 02_00736_01
R241 = 10_R_0: RES 1.87K OHM 1/10W 1% 0603 SMD; Manufacture Part Number: 0603WAF1871T5E||232270461872L; Mfg: Panasonic - ECG; Mfg Part#: ERJ-3EKF1871V; Oper. Temp. Range: -55C ~ 125C; Package: 0603; ProcessType: SMT; RoHS: Yes; Tolerance: 1%; Vendor: DigiKey; Vendor Part#: P1.87KHCT-ND; eI Part#: 02_00295_01
R242 R332 = 10_R_0: RES 53.6K OHM 1/10W 1% 0402 SMD; Manufacture Part Number: 0402WGF5622TCE||RM04FTN5622; Mfg: Panasonic - ECG; Mfg Part#: ERJ-2RKF5362X; Oper. Temp. Range: -55C ~ 125C; Package: 0402; ProcessType: SMT; RoHS: Yes; Tolerance: 1%; Vendor: DigiKey; Vendor Part#: P53.6KLCT-ND; eI Part#: 02_00737_01
R243 = 10_R_0: RES 9.09K OHM 1/10W 1% 0603 SMD; Manufacture Part Number: 0603WAF9091T5E||232270469092L; Mfg: Panasonic - ECG; Mfg Part#: ERJ-3EKF9091V; Oper. Temp. Range: -55C ~ 125C; Package: 0603; ProcessType: SMT; RoHS: Yes; Tolerance: 1%; Vendor: DigiKey; Vendor Part#: P9.09KHCT-ND; eI Part#: 02_00666_01
R244 = 10_R_0: RES 1.69K OHM 1/10W 1% 0603 SMD; Manufacture Part Number: 0603WGF1691T5E||232270461692L; Mfg: Panasonic - ECG; Mfg Part#: ERJ-3EKF1691V; Oper. Temp. Range: -55C ~ 125C; Package: 0603; ProcessType: SMT; RoHS: Yes; Tolerance: 1%; Vendor: DigiKey; Vendor Part#: P1.69KHCT-ND; eI Part#: 02_00738_01
R333 = 10_R_0: RES 2.00K OHM 1/10W 1% 0402 SMD; Alt Mfg: TE Connectivity; Alt Mfg Part#: 5-1879208-6; Mfg: Panasonic - ECG; Mfg Part#: ERJ-2RKF2001X; Oper. Temp. Range: -55C to 125C; Package: 0402; ProcessType: SMT; Remark: Alt part is 1/16W; RoHS: Yes; Tolerance: 1%; Vendor: DigiKey; Vendor Part#: P2.00KLCT-ND; eI Part#: 02_00229_02
R334 R374 = 10_R_0: RES 31.6K OHM 1/10W 1% 0402 SMD; Manufacture Part Number: RM04FTN3162; Mfg: Panasonic - ECG; Mfg Part#: ERJ-2RKF3162X; Oper. Temp. Range: -55C ~ 125C; Package: 0402; ProcessType: SMT; RoHS: Yes; Tolerance: 1%; Vendor: DigiKey; Vendor Part#: P31.6KLCT-ND; eI Part#: 02_00319_01
R221 R483 R2009 R2227-R2230 R3226 = 10_R_0: RES ZERO OHM 1/10W 5% 0402 SMD; Alt Mfg: Yageo; Alt Mfg Part#: RC0402JR-070RL; Mfg: Panasonic - ECG; Mfg Part#: ERJ-2GE0R00X; Oper. Temp. Range: -55C to 125C; Package: 0402; ProcessType: SMT; Remark: Alt part is 1/16W; RoHS: Yes; Tolerance: 5%; Vendor: DigiKey; Vendor Part#: P0.0JCT-ND; eI Part#: 02_00019_01
R1181 R1182 R1573 = RESISTOR: RES 10.0 OHM 1/10W 1% 0402 SMD; Alt Mfg: Yageo; Alt Mfg Part#: RC0402FR-0710RL; Mfg: Panasonic - ECG; Mfg Part#: ERJ-2RKF10R0X; Mounting Status: NU; Mounting_Status: NU; Oper. Temp. Range: -55C to 125C; Package: 0402; RoHS: Yes; Specifications: RES 10.0 OHM 1/10W 1% 0402 SMD; Tolerance: 1%; Vendor: DigiKey; Vendor Part#: P10.0LCT-ND; eI Part#: 02_00060_01
R2106 = 10_R_0: RES 2.2K OHM 1/10W 5% 0402 SMD; Alt Mfg: Yageo; Alt Mfg Part#: RC0402JR-072K2L; Mfg: Panasonic - ECG; Mfg Part#: ERJ-2GEJ222X; Oper. Temp. Range: -55C to 125C; Package: 0402; ProcessType: SMT; Remark: Alt part is 1/16W; RoHS: Yes; Specifications: RES 2.2K OHM 1/10W 5% 0402 SMD; Tolerance: 5%; Vendor: DigiKey; Vendor Part#: P2.2KJCT-ND; eI Part#: 02_00024_01
U29 = 141_TI_TPS54231D_0: IC BUCK ADJ 2A 8SOIC; Mfg: Texas Instruments; Mfg Part#: TPS54231DR; Oper. Temp. Range: -55C to 125C; Package: SOIC8; ProcessType: SMT; RoHS: Yes; Vendor: DigiKey; Vendor Part#: 296-23844-1-ND; eI Part#: 01_00841_01
U30 U36 = TPS54620RGY: IC BUCK SYNC ADJ 6A 14VQFN; Mfg: Texas Instruments; Oper. Temp. Range: -40°C ~ 150°C; Package: QFN14; ProcessType: SMT; RoHS: Yes; Vendor: DigiKey; Vendor Part#: 296-24554-1-ND; eI Part#: 01_00391_01
U251 U253 = 14S_TI_SN74LVC1G07_SOT-23-5: IC BUFF/DVR NON-INVERT SOT235; Mfg: Texas Instruments; Oper. Temp. Range: -40°C ~ 85°C; Package: SOT-23-5; ProcessType: SMT; RoHS: Yes; Vendor: DigiKey; Vendor Part#: 296-8485-1-ND; eI Part#: 01_00844_01
C403 = 11_C_0: CAP 10nF 16V CERAMIC 0402 SMD; Alt Mfg: Murata; Alt Mfg Part#: GRM155R71C103KA01D; Manufacture Part Number: C1005X7R1C103K||2238 787 15636||CC0402KRX7R7BB103; Mfg: Panasonic - ECG; Mfg Part#: ECJ-0EB1C103K; Oper. Temp. Range: -55C to 125C; Package: 0402; ProcessType: SMT; RoHS: Yes; Tolerance: 10%; Vendor: DigiKey; Vendor Part#: PCC103BQCT-ND; eI Part#: 03_00025_01
Q2-Q5 = TPS73701DRBT: IC REG LDO ADJ 1A 8SON; Mfg: Texas Instruments; Oper. Temp. Range: -40°C ~ 125°C; Package: SON8; ProcessType: SMT; RoHS: Yes; Vendor: DigiKey; Vendor Part#: 296-27067-1-ND; eI Part#: 01_00822_02
R222 R385 = 10_R_0: RES 28.0K OHM 1/10W 1% 0603 SMD; Manufacture Part Number: 0603WAF2802T5E||232270462803L||RM06FTN2802; Mfg: Panasonic - ECG; Mfg Part#: ERJ-3EKF2802V; Oper. Temp. Range: -55C ~ 125C; Package: 0603; ProcessType: SMT; RoHS: Yes; Tolerance: 1%; Vendor: DigiKey; Vendor Part#: P28.0KHCT-ND; eI Part#: 02_00490_02
R224 R386 = 10_R_0: RES 56.2K OHM 1/10W 1% 0603 SMD; Manufacture Part Number: 0603WAF5622T5E||232270465623L||RC0603FR-0756K2L; Mfg: Panasonic - ECG; Mfg Part#: ERJ-3EKF5622V; Oper. Temp. Range: -55C ~ 125C; Package: 0603; ProcessType: SMT; RoHS: Yes; Tolerance: 1%; Vendor: DigiKey; Vendor Part#: P56.2KHCT-ND; eI Part#: 02_00735_01
R225 = 10_R_0: RES 39.2K OHM 1/10W 1% 0603 SMD; Manufacture Part Number: 0603WAF3922T5E||2322 704 63923L; Mfg: Panasonic - ECG; Mfg Part#: ERJ-3EKF3922V; Oper. Temp. Range: -55C ~ 125C; Package: 0603; ProcessType: SMT; RoHS: Yes; Tolerance: 1%; Vendor: DigiKey; Vendor Part#: P39.2KHCT-ND; eI Part#: 02_00227_04
R227 = 10_R_0: RES 36.5K OHM 1/10W 1% 0603 SMD; Manufacture Part Number: 232270463653L||RM06FTN3652; Mfg: Panasonic - ECG; Mfg Part#: ERJ-3EKF3652V; Oper. Temp. Range: -55C ~ 125C; Package: 0603; ProcessType: SMT; RoHS: Yes; Tolerance: 1%; Vendor: DigiKey; Vendor Part#: P36.5KHCT-ND; eI Part#: 02_00231_01
U27 = TPS51200DRCT: IC SINK/SOURCE DDR REG 10-SON; Mfg: Texas Instruments; Oper. Temp. Range: -40°C ~ 85°C; Package: SON10; ProcessType: SMT; RoHS: Yes; Vendor: DigiKey; Vendor Part#: 296-23830-1-ND; eI Part#: 01_00725_02
U1131 = TPS3808G: IC VOLT SUPERVISOR 1.8V SOT23-6; Mfg: Texas Instruments; Specifications: IC VOLT SUPERVISOR 1.8V SOT23-6; Vendor: DigiKey; Vendor Part#: 296-17192-1-ND; eI Part#: 01_00401_01

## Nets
GND: 560V2_PWR1.4 560V2_PWR1.7 560V2_PWR1.8 C32.2 C327.1 C395.2 C397.2 C398.2 C399.2 C401.1 C403.2 C405.1 C406.1 C407.1 C408.1 C409.1 C410.2 C422.2 C423.2 C426.2 C427.2 C428.2 C430.2 C432.2 C433.2 C434.2 C438.2 C506.2 C507.2 C508.2 C509.2 C510.2 C513.2 C514.2 C515.2 C517.2 C523.2 C529.2 C536.2 C537.2 C538.2 C539.2 C541.2 C542.2 C544.2 C545.2 C547.2 C548.2 C549.2 C551.2 C553.2 C554.2 C1126.1 C1127.1 C1129.1 C1437.2 C2325.2 C2556.2 C2557.2 CT6.2(Negative) D7.1(ANODE) D17.2(T-) D18.1(ANODE) DC_IN1.3 Q2.4(GND) Q2.9(EPAD) Q3.4(GND) Q3.9(EPAD) Q4.4(GND) Q4.9(EPAD) Q5.4(GND) Q5.9(EPAD) R22.1 R23.1 R141.1 R223.1 R224.2 R227.2 R239.2 R240.2 R241.2 R242.1 R245.2 R332.1 R335.2 R336.2 R375.1 R386.2 R2958.1 R2959.1 TP31.1 TP32.1 TP33.1 TP34.1 U27.4(PGND) U27.8(GND) U27.11(EPAD) U29.7(GND) U30.2(GND1) U30.3(GND2) U30.15(EPAD) U36.2(GND1) U36.3(GND2) U36.15(EPAD) U244.1(GND) U251.3 U253.3 U1131.2(GND) ; also on sheet 4 5 6 7 8 9 12 16 19 20 23 26 27 28 29
VCC0V75: R2230.2 TP24.1 ; also on sheet 5
VCC0V75_EN: R23.2 U27.7(EN) ; also on sheet 29
VCC0V75_PG: R230.1 U27.9(PGOOD) ; also on sheet 29
VCC1V2: R3226.2 TP28.1 ; also on sheet 19 29
VCC1V5: C405.2 C406.2 F7.2 TP27.1 U27.2(VLDOIN) ; also on sheet 5 7 8 9
VCC1V5_EN: R375.2 U30.10(EN) ; also on sheet 29
VCC1V5_PG: R314.1 U30.14(PWRGD) ; also on sheet 29
VCC1V8: C327.2 R85.2 R957.2 R2229.2 TP21.1 U244.2(VREF1) U1131.5(SENSE) ; also on sheet 4 5 6 9 12 16 28
VCC1V8_AUX: R2227.2 R2231.2 TP22.1 ; also on sheet 6 12 26 29
VCC1V8_EN1: Q5.5(EN) R141.2 ; also on sheet 29
VCC1V8_PG: R2231.1 U1131.1(RESET#) ; also on sheet 28 29
VCC2V5: R82.1 R83.1 R142.1 R2228.2 TP20.1 ; also on sheet 19
VCC2V5_EN: Q4.5(EN) R22.2 ; also on sheet 29
VCC2V5_PG: R75.1 U251.4(OUT) ; also on sheet 29
VCC3V3_AUX: 560V2_PWR1.5 560V2_PWR1.6 C395.1 C397.1 C398.1 C399.1 C401.2 C510.1 C513.1 C536.1 C537.1 C547.1 C548.1 C554.1 C2556.1 F8.2 Q2.8(VIN) Q3.8(VIN) Q4.8(VIN) Q5.8(VIN) R21.2 R25.2 R75.2 R136.2 R230.2 R314.2 R316.2 R350.2 TP26.1 U27.10(VIN) U251.5 U253.5 U1131.6(VDD) ; also on sheet 4 6 12 16 20 23 26 27 28 29
VCC3V3_AUX_PG: R350.1 U36.14(PWRGD) ; also on sheet 29
VCC5: 560V2_PWR1.1 560V2_PWR1.2 C551.1 C553.1 F9.2 R143.2 TP25.1
VCC5_PG: R136.1 U253.4(OUT) ; also on sheet 29
VCC12: B158.1 B164.1 B165.1 C549.1 CT6.1(Positive) D18.2(CATHODE) F6.2 R374.2 R2106.1 TP30.1 ; also on sheet 12 27
VCC12_AMC: DC_IN1.2 F6.1 ; also on sheet 12
VCC_5V_EN: R2009.1 ; also on sheet 29
AMCC_P4_PCIe_RX1N: C306.1 ; also on sheet 12
AMCC_P4_PCIe_RX1P: C305.1 ; also on sheet 12
AMCC_P4_PCIe_TX1N: DSP1.AC12(PCIETXN0) ; also on sheet 12
AMCC_P4_PCIe_TX1P: DSP1.AC11(PCIETXP0) ; also on sheet 12
AMCC_P5_PCIe_RX2N: C308.1 ; also on sheet 12
AMCC_P5_PCIe_RX2P: C307.1 ; also on sheet 12
AMCC_P5_PCIe_TX2N: DSP1.AB11(PCIETXN1) ; also on sheet 12
AMCC_P5_PCIe_TX2P: DSP1.AB10(PCIETXP1) ; also on sheet 12
AMCC_P8_SRIO1_RXN: C167.1 ; also on sheet 12
AMCC_P8_SRIO1_RXP: C164.1 ; also on sheet 12
AMCC_P8_SRIO1_TXN: DSP1.AC9(RIOTXN0) ; also on sheet 12
AMCC_P8_SRIO1_TXP: DSP1.AC8(RIOTXP0) ; also on sheet 12
AMCC_P9_SRIO2_RXN: C166.1 ; also on sheet 12
AMCC_P9_SRIO2_RXP: C165.1 ; also on sheet 12
AMCC_P9_SRIO2_TXN: DSP1.AB7(RIOTXN1) ; also on sheet 12
AMCC_P9_SRIO2_TXP: DSP1.AB8(RIOTXP1) ; also on sheet 12
AMCC_P10_SRIO3_RXN: C169.1 ; also on sheet 12
AMCC_P10_SRIO3_RXP: C168.1 ; also on sheet 12
AMCC_P10_SRIO3_TXN: DSP1.AC5(RIOTXN2) ; also on sheet 12
AMCC_P10_SRIO3_TXP: DSP1.AC6(RIOTXP2) ; also on sheet 12
AMCC_P11_SRIO4_RXN: C171.1 ; also on sheet 12
AMCC_P11_SRIO4_RXP: C170.1 ; also on sheet 12
AMCC_P11_SRIO4_TXN: DSP1.AB4(RIOTXN3) ; also on sheet 12
AMCC_P11_SRIO4_TXP: DSP1.AB5(RIOTXP3) ; also on sheet 12
DSP_McBSP0_FSR: DSP1.AD24(FSR0) ; also on sheet 23 29
DSP_McBSP0_FST: DSP1.AA20(FSX0) ; also on sheet 23 29
DSP_McBSP0_RX: DSP1.AB21(DR0) R2958.2 ; also on sheet 12 23
DSP_McBSP0_RXCLK: DSP1.AA21(CLKR0) ; also on sheet 23 29
DSP_McBSP0_SLCLK: DSP1.AC23(CLKS0) ; also on sheet 23 29
DSP_McBSP0_TX: DSP1.AC22(DX0) ; also on sheet 12 23
DSP_McBSP0_TXCLK: DSP1.Y20(CLKX0) ; also on sheet 23 29
DSP_McBSP1_FSR: DSP1.AD22(FSR1) ; also on sheet 23 29
DSP_McBSP1_FST: DSP1.AE23(FSX1) ; also on sheet 23 29
DSP_McBSP1_RX: DSP1.AD21(DR1) R2959.2 ; also on sheet 12 23
DSP_McBSP1_RXCLK: DSP1.AD23(CLKR1) ; also on sheet 23 29
DSP_McBSP1_SLCLK: DSP1.AC21(CLKS1) ; also on sheet 23 29
DSP_McBSP1_TX: DSP1.AE22(DX1) ; also on sheet 12 23
DSP_McBSP1_TXCLK: DSP1.AE24(CLKX1) ; also on sheet 23 29
DSP_MDC: DSP1.AA16(MDCLK) R957.1 U244.3(SCL1)
DSP_MDIO: DSP1.AB16(MDIO) R85.1 U244.4(SDA1)
DSP_SGMII_RXN: C173.1 ; also on sheet 19
DSP_SGMII_RXP: C172.1 ; also on sheet 19
DSP_SGMII_TXN: DSP1.AC2(SGMII0TXN) ; also on sheet 19
DSP_SGMII_TXP: DSP1.AC3(SGMII0TXP) ; also on sheet 19
DSP_VREFSSTL: C403.1 U27.1(REFIN) ; also on sheet 5 8
ETH_MDC: R83.2 U244.6(SCL2) ; also on sheet 19
ETH_MDIO: R82.2 U244.5(SDA2) ; also on sheet 19
HL_REF_CLKN: DSP1.F25(MCMREFCLKOUTN) TP6.1
HL_REF_CLKP: DSP1.G25(MCMREFCLKOUTP) TP5.1
HyperLink_RXFLCLK: R456.2 ; also on sheet 23
HyperLink_RXFLDAT: DSP1.C24(MCMRXFLDAT) ; also on sheet 23
HyperLink_RXN0: C470.1 ; also on sheet 23
HyperLink_RXN1: C511.1 ; also on sheet 23
HyperLink_RXN2: C12.1 ; also on sheet 23
HyperLink_RXN3: C19.1 ; also on sheet 23
HyperLink_RXP0: C505.1 ; also on sheet 23
HyperLink_RXP1: C512.1 ; also on sheet 23
HyperLink_RXP2: C14.1 ; also on sheet 23
HyperLink_RXP3: C20.1 ; also on sheet 23
HyperLink_RXPMCLK: DSP1.E24(MCMRXPMCLK) ; also on sheet 23
HyperLink_RXPMDAT: DSP1.D24(MCMRXPMDAT) ; also on sheet 23
HyperLink_TXFLCLK: DSP1.E25(MCMTXFLCLK) ; also on sheet 23
HyperLink_TXFLDAT: DSP1.D25(MCMTXFLDAT) ; also on sheet 23
HyperLink_TXN0: DSP1.P22(MCMTXN0) ; also on sheet 23
HyperLink_TXN1: DSP1.N21(MCMTXN1) ; also on sheet 23
HyperLink_TXN2: DSP1.K22(MCMTXN2) ; also on sheet 23
HyperLink_TXN3: DSP1.J21(MCMTXN3) ; also on sheet 23
HyperLink_TXP0: DSP1.N22(MCMTXP0) ; also on sheet 23
HyperLink_TXP1: DSP1.M21(MCMTXP1) ; also on sheet 23
HyperLink_TXP2: DSP1.L22(MCMTXP2) ; also on sheet 23
HyperLink_TXP3: DSP1.K21(MCMTXP3) ; also on sheet 23
HyperLink_TXPMCLK: R457.1 ; also on sheet 23
HyperLink_TXPMDAT: DSP1.G24(MCMTXPMDAT) ; also on sheet 23
XDS560_IL: 560V2_PWR1.3 ; also on sheet 29
N36210157: C428.1 U29.4(SS)
N36210172: B158.2 C423.1 C426.1 R237.2 U29.2(VIN)
N36210179: C420.2 D7.2(CATHODE) L2.1 R1182.2 U29.8(PH)
N36210227: C422.1 C1437.1 F9.1 L2.2 R238.1
N36210235: C424.1 C427.1 U29.6(COMP)
N36210264: C424.2 R239.1
N36210276: R237.1 R240.1 R2009.2 U29.3(EN)
N36253337: Q2.3(FB) R221.2 R223.2
N36257835: C506.1 C507.1 Q2.1(VOUT) R221.1 R3226.1
N36287471: Q3.3(FB) R222.2 R224.1
N36287473: C514.1 C515.1 Q3.1(VOUT) R222.1 R2227.1
N36291863: Q4.3(FB) R225.2 R227.1
N36291869: C508.1 C509.1 Q4.1(VOUT) R225.1 R2228.1
N36361813: C410.1 U27.6(REFOUT)
N37861153: C164.2 DSP1.AE8(RIORXP0)
N37861155: C167.2 DSP1.AE9(RIORXN0)
N37861157: C165.2 DSP1.AD7(RIORXP1)
N37861159: C166.2 DSP1.AD8(RIORXN1)
N37861161: C168.2 DSP1.AE6(RIORXP2)
N37861163: C169.2 DSP1.AE5(RIORXN2)
N37861165: C170.2 DSP1.AD5(RIORXP3)
N37861167: C171.2 DSP1.AD4(RIORXN3)
N37900098: C172.2 DSP1.AE3(SGMII0RXP)
N37900100: C173.2 DSP1.AE2(SGMII0RXN)
N43940324: C511.2 DSP1.M25(MCMRXN1)
N43940327: C19.2 DSP1.K24(MCMRXN3)
N43940330: C14.2 DSP1.K25(MCMRXP2)
N43940333: C12.2 DSP1.J25(MCMRXN2)
N43940336: C20.2 DSP1.L24(MCMRXP3)
N43940590: C505.2 DSP1.N24(MCMRXP0)
N43940599: C470.2 DSP1.P24(MCMRXN0)
N43940658: C512.2 DSP1.N25(MCMRXP1)
N44510100: C431.2 L118.1 R1573.2 U36.11(PH1) U36.12(PH2)
N44510146: B165.2 C538.1 C544.1 C545.1 U36.4(PVIN1) U36.5(PVIN2) U36.6(VIN)
N44510152: R334.2 R335.1 U36.7(VSENSE)
N44510176: C431.1 U36.13(BOOT)
N44510227: C432.1 C2325.1 F8.1 L118.2 R334.1
N48150448: Q5.3(FB) R385.2 R386.1
N48150454: C517.1 C523.1 Q5.1(VOUT) R385.1 R2229.1
N49207783: R142.2 U251.2(IN)
N49213636: R143.1 U253.2(IN)
N51976334: Q3.5(EN) R25.1
N52039486: Q2.5(EN) R21.1
N65498192: DSP1.F24(MCMTXPMCLK) R457.2
N65498197: DSP1.B24(MCMRXFLCLK) R456.1
N68687080: B164.2 C529.1 C541.1 C542.1 U30.4(PVIN1) U30.5(PVIN2) U30.6(VIN)
N68687255: C429.2 L3.1 R1181.2 U30.11(PH1) U30.12(PH2)
N68687341: C429.1 U30.13(BOOT)
N69366883: D17.1(B-) R2106.2
N70134865: R316.1 U244.7(VREF2) U244.8(EN)
N70254711: R336.1 R374.1 R483.1
N70258393: R483.2 U36.10(EN)
N70262127: C438.1 U36.9(SS/TR)
N70263833: R332.2 U36.1(RT/CLK)
N70286429: R333.1 U36.8(COMP)
N70348428: C32.1 R333.2
N70401619: C420.1 U29.1(BOOT)
N70451158: R244.1 U30.8(COMP)
N70452193: R238.2 R241.1 U29.5(VSENSE)
N70456580: C430.1 C539.1 F7.1 L3.2 R243.1
N70507019: C434.1 R244.2
N70523124: R243.2 R245.1 U30.7(VSENSE)
N70558519: C433.1 U30.9(SS/TR)
N70560187: R242.2 U30.1(RT/CLK)
N70892959: C305.2 DSP1.AE11(PCIERXP0)
N70892974: C306.2 DSP1.AE12(PCIERXN0)
N70892977: C307.2 DSP1.AD11(PCIERXP1)
N70892980: C308.2 DSP1.AD10(PCIERXN1)
N71308843: C407.2 C408.2 C409.2 R2230.1 U27.3(VO) U27.5(VOSNS)
N74559400: C1126.2 R1573.1
N74713986: C1127.2 R1181.1
N74740509: C1129.2 R1182.1
N79152212: C2557.1 U1131.4(CT)

Not connected (* = marked no-connect by the designer): DC_IN1 1*; Q2 2(NC1)* 6(NC2)* 7(NC3)*; Q3 2(NC1)* 6(NC2)* 7(NC3)*; Q4 2(NC1)* 6(NC2)* 7(NC3)*; Q5 2(NC1)* 6(NC2)* 7(NC3)*; U251 1(NC)*; U253 1(NC)*; U1131 3(MR#)*

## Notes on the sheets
sheet 13
- SRIO
- Place ALL SERDES DC-blocking caps on top layer adjacent to
  the DSP's RX pins so that there are no additional vias
- SGMII
- VOLTAGE LEVEL TRANSLATOR
- PCIE
- McBSP
- HYPERLINK
- The HyperLink routes must have a max of 2 vias
  and no via stubs (Outer layer routing recommended)
sheet 14
- 12V to 3.3_AUX Generation
- VCC12
- Over Current
    Protection
- TVS
- Voltage BreakDown = 13.3V
- 3.3V_AUX @ 2.75A
- Snubber Circuit
- I(hold) = 3A
  I(trip) = 6A
  Trip time= 10.8s
- Vin =  11.5V to 12.5V
  Fsw =  900kHz
- Lmin = ((12.5 - 3.3)/(3 * 0.3) * (3.3 / (12.5 * 900kHz))
          = 2.96uH
  Co_min = (2*1) / (900kHz*0.0825)
              = 2.69uF
- Ref Ind  = 2.2uH
  Ref Cap = 32uF
- Rrt = 48000 x 900^(-0.997) - 2
        = 53.6K
- 12V to 5V Generation
- Snubber Circuit
- 5V @ 0.8A
- Vin =  11.5V to 12.5V
  Fsw =  570kHz
- Lmin = ((12.5 - 5)/(0.8 * 0.3) * (5 / (12.5 * 570kHz))
          = 21.87uH
  Co_min = 1/( 2 * 3.14 * (5/0.8)* 570kHz)
              = 44.7nF
- Ref Ind  = 22uH
  Ref Cap = 32uF
- 12V to 1.5V Generation
- XDS560 v2 Mezzanine Power
- 1.5V @ 2A
- Snubber Circuit
- Vin = 11.5V to 12.5V
  Fsw =  900KHz
- Rrt = 48000 x 900^(-0.997) - 2
        = 53.6K
- Lmin = ((12.5 - 1.5)/(2 * 0.3)) * (1.5 / (12.5*900kHz))
          = 2.44uH
  Co_min = (2*1)/(900kHz*0.075)
               = 29.62uF
- Ref Ind  = 1.2uH
  Ref Cap = 122uF
sheet 15
- 3.3V_AUX to 1.2V Generation
- 3.3V_AUX to 1.8V_AUX Generation
- 1.8V_AUX @ 0.31A
- 1.2V @ 0.6A
- R1
- R1
- R2
- R2
- Vout = (R1+R2)/R2*1.204
          = (0+10k)/10k*1.204
          = 1.204V
- Vout = (R1+R2)/R2*1.204
          = (28k+56.2k)/56.2k*1.204
          = 1.804V
- 3.3V_AUX to 2.5V Generation
- 3.3V_AUX to 1.8V Generation
- 2.5V @ 0.35A
- 1.8V @ 0.14A
- R1
- R1
- R2
- R2
- Vout = (R1+R2)/R2*1.204
          = (39.2k+36.5k)/36.5k*1.204
          = 2.50V
- Vout = (R1+R2)/R2*1.204
          = (28k+56.2k)/56.2k*1.204
          = 1.804V
- 1.8V Superviser Circuit
- 3.3V_AUX to 0.75V Generation
- 20 mil trace width
- Vth = 1.67V
- 0.75V @ 0.16A
